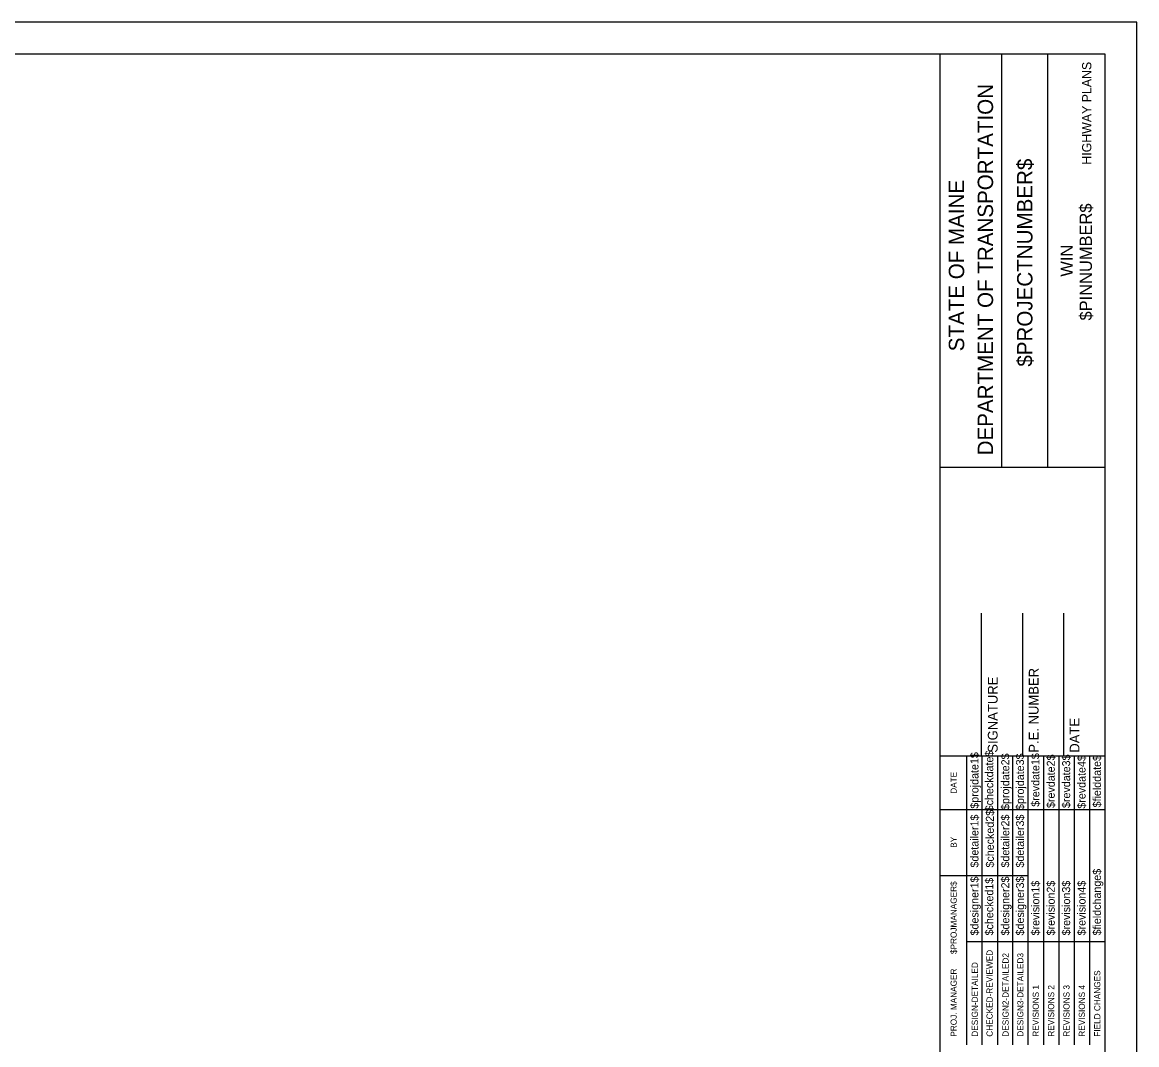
# Model space of a CAD drawing. Extents: x 850598 to 870284, y 366541 to 366651.
# Drawn here: x 856909.5 to 856977, y 366589.2 to 366651.2 of the extents above; entities that cross this region are included whole.
import ezdxf

# ---------------------------------------------------------------- set-up
doc = ezdxf.new("R2010")
doc.units = 0
for name, color, linetype in [('BORDER', 7, 'Continuous'), ('HIGHWAY_TITLE', 7, 'Continuous'), ('PLOT BOUNDARY', 7, 'Continuous')]:
    doc.layers.add(name, color=color, linetype=linetype)

msp = doc.modelspace()

# ---------------------------------------------------------------- linework, layer by layer
at = {"layer": 'BORDER'}
for p, q in [((856975.08, 366649.225), (856815.08, 366649.225)), ((856965.08, 366544.225), (856965.08, 366649.225)), ((856968.809, 366624.222), (856968.809, 366649.222)), ((856971.604, 366624.222), (856971.604, 366649.222)), ((856975.08, 366544.225), (856975.08, 366649.225)), ((856965.081, 366624.219), (856975.08, 366624.219)), ((856967.58, 366606.728), (856967.58, 366615.376)), ((856970.08, 366606.728), (856970.08, 366615.376)), ((856972.58, 366606.728), (856972.58, 366615.376)), ((856965.08, 366606.728), (856975.08, 366606.728))]:
    msp.add_line(p, q, dxfattribs=at)
for points in [[(856966.695, 366603.478), (856966.695, 366606.728)], [(856967.628, 366589.231), (856967.628, 366606.728)], [(856968.56, 366606.728), (856968.56, 366589.231)], [(856969.491, 366589.231), (856969.491, 366606.728)], [(856970.423, 366589.231), (856970.423, 366606.728)], [(856971.355, 366589.231), (856971.355, 366606.728)], [(856972.286, 366589.231), (856972.286, 366606.728)], [(856973.218, 366589.231), (856973.218, 366606.728)], [(856974.15, 366589.231), (856974.15, 366606.728)], [(856966.696, 366589.231), (856966.696, 366606.022)], [(856965.08, 366603.478), (856975.08, 366603.478)], [(856965.08, 366599.478), (856966.696, 366599.478)], [(856966.695, 366599.478), (856970.422, 366599.478)], [(856966.695, 366595.478), (856975.08, 366595.478)]]:
    msp.add_lwpolyline(points, dxfattribs=at)
at = {"layer": 'PLOT BOUNDARY'}
msp.add_lwpolyline([(856806.987, 366541.166), (856976.987, 366541.166), (856976.987, 366651.166), (856806.987, 366651.166)], close=True, dxfattribs=at)

# ---------------------------------------------------------------- texts
at = {"layer": 'BORDER'}
for s, height, p in [('DEPARTMENT OF TRANSPORTATION', 0.93176, (856968.287, 366624.931)), ('$PROJECTNUMBER$', 0.93176, (856970.672, 366630.304)), ('STATE OF MAINE', 0.93176, (856966.536, 366631.237)), ('$PINNUMBER$', 0.74527, (856974.276, 366633.1)), ('WIN', 0.7453, (856973.117, 366635.755)), ('P.E. NUMBER', 0.59055, (856971.041, 366606.92)), ('SIGNATURE', 0.5906, (856968.561, 366606.92)), ('DATE', 0.5906, (856973.521, 366606.92)), ('$checkdate$', 0.48455, (856968.298, 366603.371)), ('$projdate1$', 0.48455, (856967.403, 366603.529)), ('$projdate2$', 0.48455, (856969.267, 366603.45)), ('$projdate3$', 0.48455, (856970.161, 366603.45)), ('$revdate1$', 0.4845, (856971.093, 366603.647)), ('$revdate2$', 0.4845, (856972.024, 366603.568)), ('$revdate3$', 0.4845, (856972.956, 366603.568)), ('$revdate4$', 0.4845, (856973.888, 366603.529)), ('$fielddate$', 0.48455, (856974.82, 366603.607)), ('DATE', 0.3714, (856966.085, 366604.434)), ('$detailer1$', 0.48455, (856967.403, 366599.963)), ('$checked2$', 0.4845, (856968.335, 366599.963)), ('$detailer2$', 0.48455, (856969.267, 366599.963)), ('$detailer3$', 0.48455, (856970.161, 366599.963)), ('BY', 0.3714, (856966.085, 366601.163)), ('$fieldchange$', 0.48455, (856974.82, 366595.851)), ('$PROJMANAGER$', 0.37275, (856966.085, 366594.723)), ('$designer1$', 0.48455, (856967.403, 366595.851)), ('$checked1$', 0.4845, (856968.298, 366595.851)), ('$designer2$', 0.48455, (856969.267, 366595.851)), ('$designer3$', 0.48455, (856970.161, 366595.851)), ('$revision1$', 0.48455, (856971.093, 366595.851)), ('$revision2$', 0.48455, (856972.024, 366595.851)), ('$revision3$', 0.48455, (856972.956, 366595.851)), ('$revision4$', 0.48455, (856973.888, 366595.851)), ('CHECKED-REVIEWED', 0.37275, (856968.261, 366589.716)), ('DESIGN-DETAILED', 0.37275, (856967.367, 366589.716)), ('DESIGN2-DETAILED2', 0.37275, (856969.23, 366589.716)), ('DESIGN3-DETAILED3', 0.37275, (856970.125, 366589.716)), ('PROJ. MANAGER', 0.37275, (856966.085, 366589.716)), ('FIELD CHANGES', 0.37275, (856974.783, 366589.716)), ('REVISIONS 1', 0.37275, (856971.056, 366589.716)), ('REVISIONS 2', 0.37275, (856971.988, 366589.716)), ('REVISIONS 3', 0.37275, (856972.92, 366589.716)), ('REVISIONS 4', 0.37275, (856973.851, 366589.716))]:
    msp.add_text(s, height=height, rotation=90, dxfattribs=at).set_placement(p)
at = {"layer": 'HIGHWAY_TITLE'}
msp.add_text('HIGHWAY PLANS', height=0.55901, rotation=90, dxfattribs=at).set_placement((856974.239, 366642.541))

doc.saveas('drawing.dxf')
